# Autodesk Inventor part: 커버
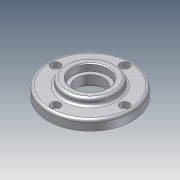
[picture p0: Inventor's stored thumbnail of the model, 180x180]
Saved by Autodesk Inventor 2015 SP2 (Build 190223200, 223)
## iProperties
Company: 한국ATC센터
Created: 2013-01
Part Number: 커버
Document SubType Name: Modeling
Designer: KYOUNG IL JANG
Density: 1 g/cm^3
Material: 일반
Appearance: 기본값
Author: KYOUNG IL JANG
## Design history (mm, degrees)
sketch "스케치1"
  geometry: C1 r 31 at (0, 0) reference; C2 r 50 at (0, 0); 1 further point
  constraints: 1 centre point, 1 coincident
  dimensions: "d41" = 100 diameter of C2
extrude "돌출1" new body sketch "스케치1" distance "d0" = 12; taper "d1" = 0 deg
sketch "스케치2"
  geometry: C1 r 30 at (0, 0); 1 further point
  constraints: 1 centre point, 1 coincident
  dimensions: "d2" = 60 diameter of C1
extrude "돌출2" join sketch "스케치2" distance "d3" = 8; taper "d4" = 0 deg
fillet "모깎기1" dims "d5" = 3
sketch "스케치3" dims "d42" = 82
  geometry: 3 further points
  constraints: 2 vertical alignment, 1 coincident, 2 other
hole "구멍1" sketch "스케치3" at (0, 41) diameter "d6" = 6.6; stored, may be unused: countersink angle "d10" = 90 deg, drill point angle "d12" = 118 deg; dims "d7" = 6, "d8" = 11, "d9" = 6.5, "d11" = 8
hole "구멍2" diameter "d18" = 33; stored, may be unused: countersink angle "d22" = 90 deg, drill point angle "d24" = 118 deg; dims "d16" = 10, "d17" = 10, "d19" = 6, "d20" = 42, "d21" = 8.5, "d23" = 8
sketch "스케치4"
  geometry: C1 r 31 at (0, 0) reference; C2 r 22.5 at (0, 0); 1 further point
  constraints: 1 centre point, 1 coincident
  dimensions: "d43" = 45 diameter of C2
extrude "돌출3" join sketch "스케치4" distance "d25" = 6; taper "d26" = 0 deg
hole "구멍3" diameter "d29" = 50; stored, may be unused: countersink angle "d33" = 90 deg, drill point angle "d35" = 0 deg; dims "d27" = 10, "d28" = 10, "d30" = 6, "d31" = 42, "d32" = 8.5, "d34" = 7
fillet "모깎기2" dims "d36" = 3, "d37" = 0.3
chamfer "모따기1" distance "d38" = 1; stored, may be unused: second distance "d39" = 2, angle "d40" = 45 deg
node "솔리드1"
pattern_circular "원형 패턴1" dims angle "d14" = 360 deg
node "참조9"
node "참조11"
